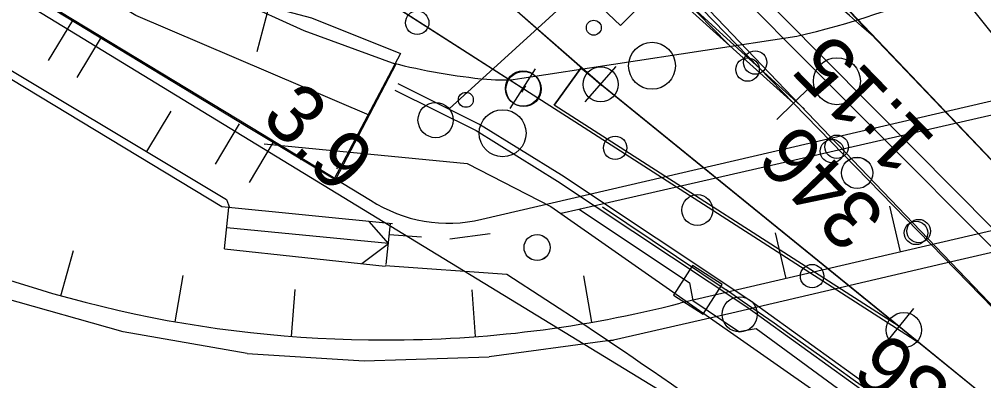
# Model space of a CAD drawing. Extents: x 1596643 to 1597288, y 13057194 to 13057957.
# Drawn here: x 1596885.06 to 1596926.19, y 13057439.15 to 13057454.55 of the extents above; entities that cross this region are included whole.
import ezdxf

# ---------------------------------------------------------------- set-up
doc = ezdxf.new("R2010")
doc.units = 0
for name, color, linetype in [('A Isolerskarv P', 7, 'Continuous'), ('A spårmitt L', 7, 'Continuous'), ('B bks2 P', 7, 'Continuous'), ('B kabelränna 400-500 mm NK L', 7, 'Continuous'), ('B växel linjevikt 0 L', 7, 'Continuous'), ('B Växel nr T', 7, 'Continuous'), ('B Växeltyp T', 7, 'Continuous'), ('BAS bro landfäste ej def L', 7, 'Continuous'), ('BAS bropelare stöd ej def L', 7, 'Continuous'), ('BAS gång- cykelväg skymd L', 7, 'Continuous'), ('BAS jvg-bro kantbalk L', 7, 'Continuous'), ('BAS jvg-bro landfäste vinge L', 7, 'Continuous'), ('BAS Level 15', 7, 'Continuous'), ('BAS Level 18', 7, 'Continuous'), ('BAS Level 19', 7, 'Continuous'), ('BAS Level 29', 7, 'Continuous'), ('BAS Level 37', 7, 'Continuous'), ('BAS markytetext T', 7, 'Continuous'), ('BAS skärmtak L', 7, 'Continuous'), ('BAS stödmur fot L', 7, 'Continuous'), ('BAS stödmur krön L', 7, 'Continuous'), ('BAS trappa L', 7, 'Continuous'), ('BAS vägbanekant L', 7, 'Continuous'), ('BAS vägbanekant skymd L', 7, 'Continuous'), ('E ktlbrygga L', 7, 'Continuous'), ('E ktlstolpe normal centrum P', 7, 'Continuous'), ('E sträva centrum P', 7, 'Continuous'), ('F signal fristående P', 7, 'Continuous')]:
    doc.layers.add(name, color=color, linetype=linetype)

msp = doc.modelspace()

# ---------------------------------------------------------------- linework, layer by layer
at = {"layer": 'A Isolerskarv P'}
for centre in [(1596909.849, 13057451.778), (1596909.849, 13057451.778), (1596906.536, 13057451.603), (1596906.536, 13057451.603), (1596922.78, 13057441.312), (1596922.78, 13057441.312)]:
    msp.add_circle(centre, 0.75, dxfattribs=at)
at = {"layer": 'A spårmitt L'}
for p, q in [((1596908.746, 13057450.177), (1596874.893, 13057471.888)), ((1596906.645, 13057451.716), (1596906.471, 13057451.445)), ((1596932.423, 13057433.479), (1596909.882, 13057451.74)), ((1596923.456, 13057440.743), (1596908.746, 13057450.177))]:
    msp.add_line(p, q, dxfattribs=at)
for points in [[(1596861.603, 13057516.009), (1596866.442, 13057509.391), (1596878.849, 13057493.781), (1596895.097, 13057475.302), (1596900.34, 13057469.714), (1596931.231, 13057437.468), (1596933.8, 13057434.835)], [(1596887.988, 13057492.75), (1596889.66, 13057490.516), (1596900.094, 13057476.776), (1596906.53, 13057469.464), (1596928.328, 13057446.663), (1596936.899, 13057437.942), (1596957.336, 13057417.351), (1597001.928, 13057371.989), (1597034.879, 13057338.506), (1597063.764, 13057309.15)], [(1596870.725, 13057487.218), (1596871.41, 13057486.548), (1596888.081, 13057470.874), (1596909.882, 13057451.74)], [(1596886.976, 13057479.839), (1596899.114, 13057468.402), (1596918.539, 13057450.716)], [(1596907.066, 13057477.919), (1596920.191, 13057461.87), (1596938.351, 13057439.217), (1596949.208, 13057425.541)]]:
    msp.add_lwpolyline(points, dxfattribs=at)
msp.add_spline([(1596921.486, 13057453.819), (1596905.281, 13057468.17), (1596896.354, 13057476.52), (1596877.996, 13057494.854)], degree=3, dxfattribs=at)
at = {"layer": 'B bks2 P'}
msp.add_circle((1596906.563, 13057451.581), 0.75, dxfattribs=at)
msp.add_circle((1596906.563, 13057451.581), 0.75, dxfattribs=at)
at = {"layer": 'B kabelränna 400-500 mm NK L'}
for points in [[(1596883.038, 13057480.441), (1596889.091, 13057474.53), (1596902.563, 13057461.987), (1596910.703, 13057454.289), (1596911.093, 13057454.69), (1596913.886, 13057457.525), (1596927.553, 13057443.815), (1596936.728, 13057434.552), (1596947.807, 13057423.165), (1596958.841, 13057412.087), (1596959.17, 13057412.506), (1596945.763, 13057426.086), (1596935.532, 13057436.607), (1596925.003, 13057447.233), (1596913.927, 13057458.386), (1596910.643, 13057455.068), (1596902.92, 13057462.372), (1596891.14, 13057473.364), (1596883.436, 13057480.826)], [(1596957.805, 13057407.362), (1596950.51, 13057414.544), (1596951.246, 13057415.209), (1596949.857, 13057416.542), (1596949.236, 13057415.819), (1596945.8, 13057419.005), (1596946.118, 13057419.283), (1596941.482, 13057423.417), (1596941.206, 13057423.108), (1596936.058, 13057427.512), (1596924.93, 13057436.294), (1596916.256, 13057442.547), (1596908.178, 13057447.912), (1596904.689, 13057450.072), (1596901.208, 13057451.804)], [(1596901.074, 13057451.536), (1596904.542, 13057449.81), (1596908.016, 13057447.659), (1596916.085, 13057442.301), (1596924.749, 13057436.055), (1596935.868, 13057427.28), (1596941.234, 13057422.69), (1596941.234, 13057422.69), (1596944.99, 13057419.335), (1596949.26, 13057415.387), (1596950.073, 13057414.553), (1596957.594, 13057407.148)]]:
    msp.add_lwpolyline(points, dxfattribs=at)
at = {"layer": 'B växel linjevikt 0 L'}
for p, q in [((1596918.078, 13057450.985), (1596899.769, 13057469.795)), ((1596918.078, 13057450.985), (1596899.769, 13057469.795)), ((1596915.283, 13057453.497), (1596899.595, 13057469.615)), ((1596915.283, 13057453.497), (1596899.595, 13057469.615)), ((1596918.078, 13057450.985), (1596898.558, 13057468.536)), ((1596918.078, 13057450.985), (1596898.558, 13057468.536)), ((1596928.31, 13057446.676), (1596915.42, 13057460.223)), ((1596928.31, 13057446.676), (1596915.42, 13057460.223)), ((1596909.846, 13057451.785), (1596901.173, 13057459.397)), ((1596909.846, 13057451.785), (1596901.173, 13057459.397)), ((1596906.533, 13057451.597), (1596896.82, 13057457.828)), ((1596906.533, 13057451.597), (1596896.82, 13057457.828)), ((1596909.007, 13057452.464), (1596907.874, 13057450.898)), ((1596909.007, 13057452.464), (1596907.874, 13057450.898)), ((1596907.874, 13057450.898), (1596909.007, 13057452.464)), ((1596909.007, 13057452.464), (1596907.874, 13057450.898)), ((1596922.579, 13057441.457), (1596909.007, 13057452.464)), ((1596922.579, 13057441.457), (1596909.007, 13057452.464)), ((1596922.579, 13057441.457), (1596909.007, 13057452.464)), ((1596909.186, 13057451.033), (1596910.506, 13057452.537)), ((1596909.186, 13057451.033), (1596910.506, 13057452.537)), ((1596905.993, 13057450.755), (1596907.073, 13057452.439)), ((1596905.993, 13057450.755), (1596907.073, 13057452.439)), ((1596918.794, 13057451.682), (1596917.361, 13057450.287)), ((1596918.794, 13057451.682), (1596917.361, 13057450.287)), ((1596922.579, 13057441.457), (1596907.874, 13057450.898)), ((1596922.579, 13057441.457), (1596907.874, 13057450.898)), ((1596930.874, 13057437.838), (1596918.078, 13057450.985)), ((1596930.874, 13057437.838), (1596918.078, 13057450.985)), ((1596921.949, 13057440.68), (1596923.209, 13057442.234)), ((1596921.949, 13057440.68), (1596923.209, 13057442.234)), ((1596931.542, 13057434.188), (1596922.579, 13057441.457)), ((1596931.542, 13057434.188), (1596922.579, 13057441.457))]:
    msp.add_line(p, q, dxfattribs=at)
at = {"layer": 'BAS bro landfäste ej def L'}
for p, q in [((1596909.929, 13057446.56), (1596915.202, 13057443.018)), ((1596900.835, 13057445.381), (1596902.212, 13057445.287)), ((1596903.424, 13057445.204), (1596905.139, 13057445.425))]:
    msp.add_line(p, q, dxfattribs=at)
msp.add_lwpolyline([(1596909.929, 13057446.56), (1596915.202, 13057443.018)], dxfattribs=at)
at = {"layer": 'BAS bropelare stöd ej def L'}
for centre, radius in [((1596920.787, 13057448.004), 0.667), ((1596920.788, 13057448.004), 0.666), ((1596913.973, 13057446.424), 0.66), ((1596913.973, 13057446.424), 0.66), ((1596907.138, 13057444.828), 0.556), ((1596907.138, 13057444.828), 0.555)]:
    msp.add_circle(centre, radius, dxfattribs=at)
at = {"layer": 'BAS gång- cykelväg skymd L'}
for p, q in [((1596906.486, 13057452.037), (1596918.21, 13057453.831)), ((1596904.78, 13057446.035), (1596929.935, 13057451.867)), ((1596898.447, 13057447.804), (1596900.039, 13057446.845))]:
    msp.add_line(p, q, dxfattribs=at)
for centre, radius, start, end in [((1596910.337, 13057488.382), 35.437, 282.8368, 294.0319), ((1596907.636, 13057479.159), 27.291, 255.8592, 264.4533), ((1596905.578, 13057457.968), 6, 264.4537, 278.7004), ((1596903.352, 13057451.953), 6.089, 237.0337, 283.5615)]:
    msp.add_arc(centre, radius, start, end, dxfattribs=at)
at = {"layer": 'BAS jvg-bro kantbalk L'}
for centre, radius, start, end in [((1596754.249, 13057209.032), 283.999, 44.7736, 55.47706), ((1596747.882, 13057200.444), 290.055, 49.94104, 56.21521)]:
    msp.add_arc(centre, radius, start, end, dxfattribs=at)
at = {"layer": 'BAS jvg-bro landfäste vinge L'}
msp.add_lwpolyline([(1596908.173, 13057446.295), (1596908.918, 13057446.461), (1596937.924, 13057453.08)], dxfattribs=at)
at = {"layer": 'BAS Level 15'}
for centre in [(1596902.026, 13057454.406), (1596902.026, 13057454.406), (1596916.116, 13057452.411), (1596916.116, 13057452.411), (1596916.44, 13057452.71), (1596916.44, 13057452.71), (1596910.469, 13057449.075), (1596910.469, 13057449.075), (1596919.915, 13057449.118), (1596919.915, 13057449.118), (1596919.716, 13057448.935), (1596919.716, 13057448.935), (1596923.298, 13057445.45), (1596923.298, 13057445.45), (1596923.414, 13057445.526), (1596923.414, 13057445.526), (1596918.868, 13057443.608), (1596918.868, 13057443.608)]:
    msp.add_circle(centre, 0.5, dxfattribs=at)
at = {"layer": 'BAS Level 18'}
for p, q in [((1596895.704, 13057455.098), (1596895.183, 13057453.167)), ((1596895.704, 13057455.098), (1596895.183, 13057453.167)), ((1596887.326, 13057454.498), (1596886.288, 13057452.789)), ((1596887.326, 13057454.498), (1596886.288, 13057452.789)), ((1596888.551, 13057453.783), (1596887.517, 13057452.071)), ((1596888.551, 13057453.783), (1596887.517, 13057452.071)), ((1596891.515, 13057450.632), (1596890.487, 13057448.916)), ((1596891.515, 13057450.632), (1596890.487, 13057448.916)), ((1596893.418, 13057448.383), (1596894.453, 13057450.095)), ((1596893.418, 13057448.383), (1596894.453, 13057450.095)), ((1596895.878, 13057449.316), (1596894.854, 13057447.598)), ((1596895.878, 13057449.316), (1596894.854, 13057447.598)), ((1596908.937, 13057446.462), (1596913.646, 13057443.324)), ((1596922.632, 13057444.638), (1596922.178, 13057446.586)), ((1596922.632, 13057444.638), (1596922.178, 13057446.586)), ((1596917.762, 13057443.504), (1596917.308, 13057445.452)), ((1596917.762, 13057443.504), (1596917.308, 13057445.452)), ((1596886.832, 13057442.772), (1596887.371, 13057444.698)), ((1596886.832, 13057442.772), (1596887.371, 13057444.698)), ((1596891.705, 13057441.664), (1596892.052, 13057443.634)), ((1596891.705, 13057441.664), (1596892.052, 13057443.634)), ((1596909.475, 13057441.646), (1596909.131, 13057443.616)), ((1596909.475, 13057441.646), (1596909.131, 13057443.616)), ((1596896.664, 13057441.04), (1596896.816, 13057443.034)), ((1596896.664, 13057441.04), (1596896.816, 13057443.034)), ((1596904.515, 13057441.031), (1596904.367, 13057443.026)), ((1596904.515, 13057441.031), (1596904.367, 13057443.026)), ((1596913.646, 13057443.324), (1596913.782, 13057442.568)), ((1596913.782, 13057442.568), (1596915.74, 13057441.248)), ((1596915.74, 13057441.248), (1596916.482, 13057441.38)), ((1596916.482, 13057441.38), (1596927.247, 13057433.495))]:
    msp.add_line(p, q, dxfattribs=at)
msp.add_lwpolyline([(1596873.304, 13057459.15), (1596875.811, 13057457.691), (1596882.485, 13057453.708), (1596893.896, 13057446.874), (1596894.027, 13057446.528)], dxfattribs=at)
at = {"layer": 'BAS Level 19'}
for p, q in [((1596895.493, 13057449.247), (1596904.152, 13057448.405)), ((1596904.152, 13057448.405), (1596907.73, 13057446.575)), ((1596907.73, 13057446.575), (1596924.451, 13057434.896))]:
    msp.add_line(p, q, dxfattribs=at)
at = {"layer": 'BAS Level 29'}
for centre in [(1596909.558, 13057454.193), (1596909.558, 13057454.193), (1596904.102, 13057451.12), (1596904.102, 13057451.12)]:
    msp.add_circle(centre, 0.318, dxfattribs=at)
at = {"layer": 'BAS Level 37'}
msp.add_lwpolyline([(1596878.914, 13057459.15), (1596920.541, 13057433.769), (1596934.167, 13057425.381), (1596938.443, 13057422.802), (1596956.991, 13057405.807)], dxfattribs=at)
at = {"layer": 'BAS skärmtak L'}
for p, q in [((1596893.814, 13057444.768), (1596893.988, 13057446.53)), ((1596900.798, 13057445.005), (1596899.983, 13057445.936)), ((1596900.709, 13057444.109), (1596900.881, 13057445.848)), ((1596899.667, 13057444.143), (1596900.798, 13057445.005))]:
    msp.add_line(p, q, dxfattribs=at)
at = {"layer": 'BAS stödmur fot L'}
for p, q in [((1596893.69, 13057446.559), (1596863.227, 13057464.952)), ((1596900.978, 13057445.838), (1596893.69, 13057446.559))]:
    msp.add_line(p, q, dxfattribs=at)
for points in [[(1596878.129, 13057460.111), (1596886.781, 13057454.877), (1596895.436, 13057449.654), (1596898.551, 13057447.748)], [(1596894.311, 13057455.398), (1596897.186, 13057454.067), (1596901.11, 13057452.644)], [(1596901.11, 13057452.644), (1596898.551, 13057447.748)], [(1596898.623, 13057448.177), (1596898.59, 13057448.211)]]:
    msp.add_lwpolyline(points, dxfattribs=at)
at = {"layer": 'BAS stödmur krön L'}
for p, q in [((1596936.897, 13057447.961), (1596913.236, 13057442.45)), ((1596905.848, 13057443.684), (1596900.665, 13057444.045)), ((1596909.175, 13057441.518), (1596905.848, 13057443.684))]:
    msp.add_line(p, q, dxfattribs=at)
for points in [[(1596869.429, 13057469.233), (1596873.974, 13057466.314), (1596882.404, 13057461.272), (1596891.584, 13057456.105), (1596894.279, 13057455.482), (1596897.513, 13057454.611), (1596901.314, 13057453.101)], [(1596878.787, 13057459.703), (1596884.705, 13057456.09), (1596894.812, 13057449.952), (1596898.489, 13057447.759)], [(1596901.314, 13057453.101), (1596898.489, 13057447.759)]]:
    msp.add_lwpolyline(points, dxfattribs=at)
for centre, radius, start, end in [((1596900.529, 13057491.753), 50.86, 244.2248, 270.1611), ((1596900.782, 13057491.473), 50.58, 269.875, 284.2538)]:
    msp.add_arc(centre, radius, start, end, dxfattribs=at)
at = {"layer": 'BAS trappa L'}
for p, q in [((1596900.798, 13057445.005), (1596893.903, 13057445.664)), ((1596893.814, 13057444.768), (1596900.661, 13057444.037))]:
    msp.add_line(p, q, dxfattribs=at)
msp.add_lwpolyline([(1596899.981, 13057450.473), (1596890.028, 13057454.706), (1596868.532, 13057467.716)], dxfattribs=at)
at = {"layer": 'BAS vägbanekant L'}
for p, q in [((1596889.488, 13057441.236), (1596884.358, 13057442.682)), ((1596894.779, 13057440.311), (1596889.488, 13057441.236)), ((1596894.779, 13057440.311), (1596899.769, 13057439.999)), ((1596899.769, 13057439.999), (1596905.09, 13057440.17))]:
    msp.add_line(p, q, dxfattribs=at)
for points in [[(1596889.488, 13057441.236), (1596884.358, 13057442.682)], [(1596894.779, 13057440.311), (1596889.488, 13057441.236)], [(1596910.146, 13057440.853), (1596905.09, 13057440.17)], [(1596894.779, 13057440.311), (1596899.769, 13057439.999)], [(1596899.769, 13057439.999), (1596905.09, 13057440.17)]]:
    msp.add_lwpolyline(points, dxfattribs=at)
at = {"layer": 'BAS vägbanekant skymd L'}
msp.add_lwpolyline([(1596975.549, 13057456.294), (1596969.153, 13057454.536), (1596962.688, 13057453.046), (1596957.894, 13057451.93), (1596953.113, 13057450.794), (1596943.549, 13057448.559), (1596937.074, 13057447.044), (1596934.001, 13057446.332), (1596924.437, 13057444.133), (1596915.451, 13057442.034), (1596910.392, 13057440.886), (1596910.146, 13057440.853), (1596910.392, 13057440.886)], dxfattribs=at)
at = {"layer": 'E ktlbrygga L'}
msp.add_lwpolyline([(1596921.564, 13057467.262), (1596903.383, 13057450.74)], dxfattribs=at)
at = {"layer": 'E ktlstolpe normal centrum P'}
for centre in [(1596902.81, 13057450.256), (1596902.81, 13057450.256), (1596915.781, 13057441.978), (1596915.781, 13057441.978)]:
    msp.add_circle(centre, 0.75, dxfattribs=at)
at = {"layer": 'E sträva centrum P'}
for p, q in [((1596913.765, 13057444.066), (1596912.955, 13057442.804)), ((1596913.765, 13057444.066), (1596912.955, 13057442.804)), ((1596915.027, 13057443.256), (1596913.765, 13057444.066)), ((1596915.027, 13057443.256), (1596913.765, 13057444.066)), ((1596913.991, 13057443.03), (1596913.991, 13057443.03)), ((1596913.991, 13057443.03), (1596913.991, 13057443.03)), ((1596914.217, 13057441.994), (1596915.027, 13057443.256)), ((1596914.217, 13057441.994), (1596915.027, 13057443.256)), ((1596912.955, 13057442.804), (1596914.217, 13057441.994)), ((1596912.955, 13057442.804), (1596914.217, 13057441.994))]:
    msp.add_line(p, q, dxfattribs=at)
at = {"layer": 'F signal fristående P'}
for centre in [(1596912.041, 13057452.57), (1596912.041, 13057452.57), (1596919.927, 13057451.914), (1596919.927, 13057451.914), (1596905.669, 13057449.696), (1596905.669, 13057449.696)]:
    msp.add_circle(centre, 1, dxfattribs=at)

# ---------------------------------------------------------------- texts
at = {"layer": 'B Växel nr T'}
for s, height, rotation, p in [('346', 2.499, 133.767, (1596922.093, 13057446.208)), ('336', 2.5, 140.985, (1596926.383, 13057437.805))]:
    msp.add_text(s, height=height, rotation=rotation, dxfattribs=at).set_placement(p)
at = {"layer": 'B Växeltyp T'}
msp.add_text('1:15', height=2.5, rotation=134.226, dxfattribs=at).set_placement((1596924.213, 13057449.423))
at = {"layer": 'BAS markytetext T'}
msp.add_text('3.9', height=2.5, rotation=315, dxfattribs=at).set_placement((1596895.312, 13057450.299))

doc.saveas('drawing.dxf')
